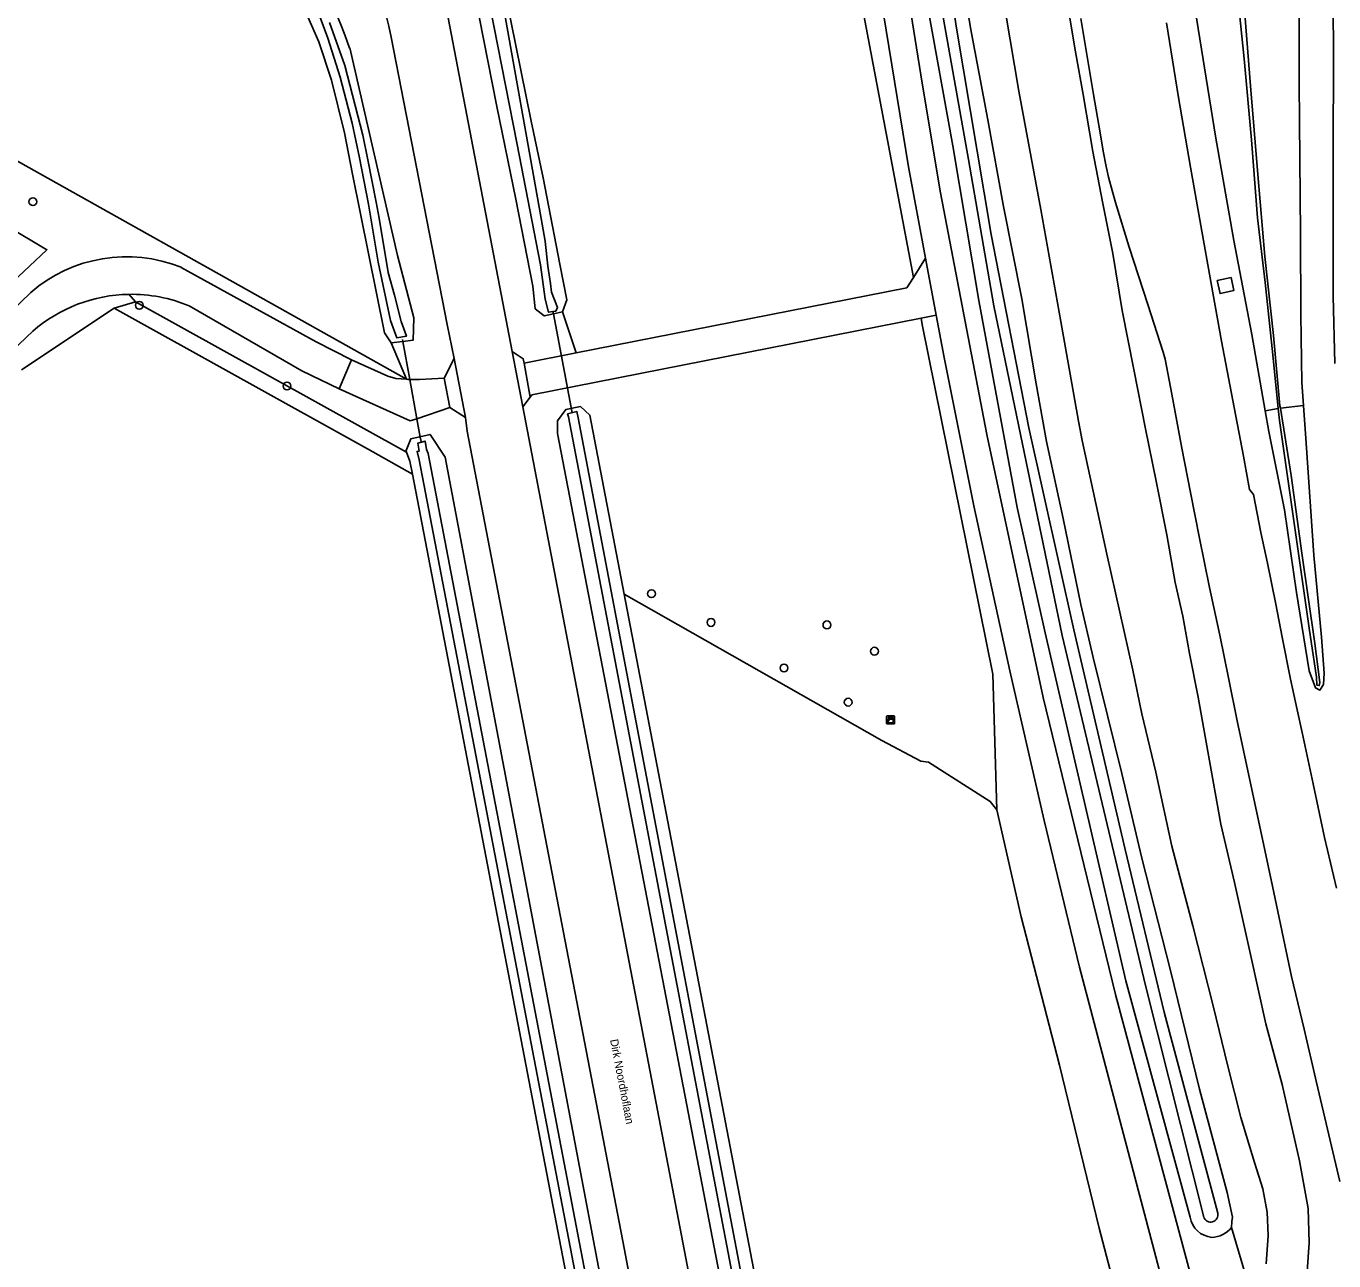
# Model space of a CAD drawing. Extents: x 155209 to 156823, y 385356 to 388482.
# Drawn here: x 155935 to 156098.5, y 387163 to 387317.3 of the extents above; entities that cross this region are included whole.
import ezdxf

# ---------------------------------------------------------------- set-up
doc = ezdxf.new("R2010")
doc.units = 0
for name, color, linetype in [('IMGEO_Berm_groen', 7, 'Continuous'), ('IMGEO_Boom', 7, 'Continuous'), ('IMGEO_Bouwland', 7, 'Continuous'), ('IMGEO_Duiker', 7, 'Continuous'), ('IMGEO_Grasland_overig', 7, 'Continuous'), ('IMGEO_Groenvoorziening', 7, 'Continuous'), ('IMGEO_Kast', 7, 'Continuous'), ('IMGEO_Openbare_ruimte_label', 7, 'Continuous'), ('IMGEO_Rijbaan_autoweg', 7, 'Continuous'), ('IMGEO_Rijbaan_lokaal_gesloten', 7, 'Continuous'), ('IMGEO_Rijbaan_lokaal_halfverhard', 7, 'Continuous'), ('IMGEO_Rijbaan_lokaal_onverhard', 7, 'Continuous'), ('IMGEO_Rijbaan_lokaal_open', 7, 'Continuous'), ('IMGEO_Struiken', 7, 'Continuous'), ('IMGEO_Waterloop', 7, 'Continuous')]:
    doc.layers.add(name, color=color, linetype=linetype)

msp = doc.modelspace()

# ---------------------------------------------------------------- linework, layer by layer
at = {"layer": 'IMGEO_Berm_groen'}
for points in [[(156061.62, 387476.82), (156062.41, 387469.09), (156063.7, 387456.14), (156064.93, 387442.53), (156066.52, 387426.48), (156068.23, 387413.01), (156069.84, 387398.7), (156071, 387388.31), (156072.33, 387377.8), (156074.13, 387364.9), (156075.6, 387353.79), (156077.6, 387340.98), (156079.75, 387327.89), (156081.71, 387315.66), (156083.71, 387303.27), (156085.96, 387290.47), (156088.22, 387278.73), (156089.87, 387269.17)], [(156091.79, 387269.51), (156091.73, 387269.83), (156090.93, 387278.61), (156089.85, 387288.48), (156088.98, 387298.73), (156088.03, 387309.82), (156087.34, 387318.75), (156086.57, 387326.51), (156086.11, 387337.21), (156085.57, 387346.45), (156085.53, 387353.44), (156085.58, 387363.28), (156085.48, 387373.43), (156085.38, 387384.38), (156085.39, 387393.87), (156085.5, 387398.4), (156085.73, 387399.51), (156086.28, 387400.46)], [(156095.62, 387391.04), (156095.67, 387380.15), (156095.25, 387368.03), (156095.02, 387355.31), (156094.88, 387346.18), (156094.52, 387336.14), (156094.14, 387326.16), (156094.14, 387318.25), (156094.11, 387310.18), (156094.22, 387300.65), (156094.28, 387291.34), (156094.35, 387281.23), (156094.46, 387272.73), (156094.68, 387269.84)], [(156091.51, 387269.47), (156090.82, 387276.17), (156089.88, 387285.21), (156088.93, 387293.32), (156088.19, 387303.06), (156087.26, 387313.19), (156086.23, 387323.35)], [(156064.83, 387322.06), (156066.18, 387314.05), (156067.13, 387308.73), (156068.35, 387301.58), (156069.57, 387295.29), (156070.85, 387288.86), (156072.01, 387281.71), (156073.46, 387274.35), (156074.91, 387266.93), (156076.27, 387260.41), (156077.57, 387253.69), (156078.65, 387247.72), (156079.57, 387243.53), (156080.41, 387238.88), (156081.52, 387233.39), (156082.94, 387225.44), (156084.32, 387217.55), (156086.06, 387210.27), (156088.06, 387201.26), (156089.96, 387192.59), (156092.02, 387185.03), (156094.18, 387175.46), (156095.27, 387169.51), (156095.39, 387165.23), (156095.04, 387160.42)], [(156085.62, 387285.86), (156083.89, 387285.47), (156084.25, 387283.85), (156085.98, 387284.24), (156085.62, 387285.86)], [(155947.88, 387283.75), (155948.71, 387282.8)], [(155946.02, 387282), (155934.44, 387274.3)], [(155948.71, 387282.8), (155946.02, 387282)], [(155948.71, 387282.8), (155982.58, 387264.03)], [(156089.87, 387269.17), (156090.32, 387266.61), (156092.28, 387256.8), (156093.78, 387246.51), (156095.36, 387236.69), (156096.17, 387234.57), (156096.72, 387234.3), (156097.16, 387235.01), (156097.27, 387236.41), (156096.9, 387240.92), (156095.95, 387251.17), (156095, 387265.15), (156094.68, 387269.84)], [(156091.79, 387269.51), (156093.12, 387261.1), (156094.44, 387251.42), (156096.1, 387240.13), (156096.69, 387235.24), (156096.63, 387234.85), (156096.34, 387234.9), (156096.31, 387235.92), (156095.38, 387242.03), (156093.61, 387254.26), (156091.67, 387267.98), (156091.51, 387269.47)], [(156020.54, 387071.32), (156022.07, 387071.71), (156023.15, 387072.76), (156023.19, 387074.38), (155987.41, 387263.41), (155985.52, 387266.24), (155983.11, 387265.71), (155982.51, 387264.23), (155982.58, 387264.03)]]:
    msp.add_lwpolyline(points, dxfattribs=at)
at = {"layer": 'IMGEO_Boom'}
for centre in [(155935.88, 387295.32), (155949.18, 387282.38), (155967.63, 387272.3), (156013.19, 387246.34), (156020.63, 387242.75), (156035.11, 387242.44), (156041.05, 387239.15), (156029.74, 387237.05), (156037.77, 387232.78)]:
    msp.add_circle(centre, 0.489, dxfattribs=at)
at = {"layer": 'IMGEO_Bouwland'}
for points in [[(155700.58, 387559.16), (155705.83, 387556.93), (155969.17, 387436.11), (155980.49, 387430.9), (156014.09, 387415.4), (156016.16, 387414.21), (156018.36, 387412.83), (156019.97, 387411.04), (156020.38, 387409.71), (156021.3, 387407.09), (156021.62, 387404.48), (156021.21, 387401.4), (156020.2, 387398.6), (155995.77, 387345.63), (155992.84, 387339.75), (155992.29, 387338.15), (155992.33, 387336.17), (155993.02, 387331.58), (155994.35, 387324.15), (155998.16, 387305.37), (155999.63, 387298.3), (156001.74, 387287.51), (156002.6, 387283.08), (156002.07, 387281.58)], [(156045.92, 387285.85), (156037.65, 387329.66), (156026.8, 387420.55), (156020.19, 387555.62)], [(155969.78, 387319.47), (155971.62, 387315.3), (155973.18, 387310.52), (155974.83, 387303.91), (155975.84, 387298.77), (155979.82, 387278.93), (155980.66, 387277.68)], [(155852.44, 387209.14), (155937.64, 387289.31), (155917.27, 387301.48), (155920.84, 387307.7), (155982.59, 387273.13)], [(155983.31, 387261.26), (155977.7, 387264.44), (155946.02, 387282)], [(156002.07, 387281.58), (156003.77, 387276.42)], [(156056.35, 387219.32), (156055.84, 387236.29), (156047.02, 387279.97), (156046.87, 387280.78)], [(155982.59, 387273.13), (155980.66, 387277.68)], [(156040.62, 387085.43), (156049.4, 387039.61), (156049.03, 387038.45), (156048.01, 387037.48), (156046.7, 387037.25), (156045.6, 387038.35), (156044.88, 387040.73), (156001.43, 387266.35), (156001.45, 387267.92), (156002.48, 387269.35), (156004.33, 387269.73), (156005.47, 387268.66), (156009.77, 387246.27)], [(155983.31, 387261.26), (156019.65, 387072.07), (156020.54, 387071.32)], [(156009.77, 387246.27), (156039.37, 387091.89)], [(156009.77, 387246.27), (156041.99, 387228.01), (156046.85, 387225.4), (156047.8, 387225.28), (156055.53, 387220.36), (156056.35, 387219.32)], [(156078.96, 387129.05), (156077.06, 387135.76), (156072.99, 387152.28), (156069.14, 387167.07), (156064.17, 387187.41), (156059.38, 387205.95), (156056.35, 387219.32)]]:
    msp.add_lwpolyline(points, dxfattribs=at)
at = {"layer": 'IMGEO_Duiker'}
for points in [[(156000.87, 387281.6), (156000.93, 387281.32), (156003.27, 387268.94)], [(155982.06, 387278.09), (155982.1, 387277.85), (155982.97, 387273.12), (155983.87, 387268.2), (155984.28, 387265.92), (155984.39, 387265.37)]]:
    msp.add_lwpolyline(points, dxfattribs=at)
at = {"layer": 'IMGEO_Grasland_overig'}
for points in [[(156085.66, 387167.13), (156085.73, 387167.9), (156085.79, 387168.45), (156085.12, 387171.5), (156081.69, 387184.41), (156078.03, 387199.27), (156074.47, 387213.29), (156071.98, 387223.87), (156068.39, 387238.38), (156066.86, 387244.97), (156064.64, 387255.74), (156062.57, 387265.36), (156061.25, 387272.56), (156059.48, 387283.2), (156057.16, 387294.73), (156055.2, 387305.56), (156053.06, 387317.03), (156051.56, 387326.11)], [(156090, 387162.62), (156090.26, 387166.15), (156090.13, 387169.04), (156089.57, 387171.99), (156088.55, 387175.26), (156086.83, 387180.87), (156085.22, 387187.3), (156083.39, 387194.86), (156080.83, 387204.83), (156078.22, 387214.79), (156076.2, 387224.02), (156074.47, 387231.32), (156073.33, 387236.78), (156070.1, 387251.29), (156067, 387265.48), (156066.57, 387267.88), (156064.33, 387280.36), (156061.83, 387294.35), (156059.1, 387309.12), (156056.92, 387322)], [(156080.49, 387168.45), (156072.47, 387197.97), (156062.39, 387241.43), (156058.9, 387257.1), (156054.08, 387282.98), (156050.84, 387302.29), (156047.64, 387320.03)], [(156095.73, 387133.19), (156085.66, 387167.13)]]:
    msp.add_lwpolyline(points, dxfattribs=at)
for centre, radius, start, end in [((156083.5, 387168.93), 3.04, 189.1217, 264.4738), ((156083.09, 387169.19), 3.29, 272.035, 321.3376)]:
    msp.add_arc(centre, radius, start, end, dxfattribs=at)
at = {"layer": 'IMGEO_Groenvoorziening'}
for points in [[(156002.07, 387281.58), (156000.93, 387281.32), (155999.78, 387281.05), (155998.63, 387281.95), (155998.35, 387284.75), (155997.67, 387288.39), (155996.23, 387295.64), (155993.85, 387307.21), (155991.64, 387318.41), (155989.37, 387330.86)], [(155980.66, 387277.68), (155982.1, 387277.85), (155983.39, 387278.01), (155983.5, 387280.81), (155981.46, 387288.59), (155975.47, 387314.53)], [(155982.58, 387264.03), (155983, 387262.89), (155983.31, 387261.26)]]:
    msp.add_lwpolyline(points, dxfattribs=at)
msp.add_arc((155897.75, 387286.71), 82.54, 19.6901, 30.7711, dxfattribs=at)
at = {"layer": 'IMGEO_Kast'}
for p, q in [((156042.57, 387230.14), (156042.57, 387230.98)), ((156042.57, 387230.98), (156042.57, 387230.14)), ((156042.65, 387231.06), (156043.49, 387231.06)), ((156043.49, 387231.06), (156042.65, 387231.06)), ((156043.5, 387230.06), (156042.66, 387230.06)), ((156042.66, 387230.06), (156043.5, 387230.06)), ((156043.57, 387230.99), (156043.57, 387230.15)), ((156043.57, 387230.15), (156043.57, 387230.99))]:
    msp.add_line(p, q, dxfattribs=at)
for points in [[(156042.77, 387230.85), (156043.37, 387230.85), (156043.37, 387230.77), (156042.77, 387230.77), (156042.77, 387230.85)], [(156042.77, 387230.68), (156043.37, 387230.68), (156043.37, 387230.19), (156042.77, 387230.19), (156042.77, 387230.68)]]:
    msp.add_lwpolyline(points, dxfattribs=at)
msp.add_circle((156042.85, 387230.53), 0.0377, dxfattribs=at)
for centre, start, end in [((156042.65, 387230.99), 92.4484, 184.2845), ((156042.65, 387230.99), 92.4484, 184.2845), ((156042.65, 387230.14), 182.4484, 274.2845), ((156042.65, 387230.14), 182.4484, 274.2845), ((156043.49, 387230.99), 2.4484, 94.2845), ((156043.49, 387230.99), 2.4484, 94.2845), ((156043.49, 387230.14), 272.4484, 4.2845), ((156043.49, 387230.14), 272.4484, 4.2845)]:
    msp.add_arc(centre, 0.0779, start, end, dxfattribs=at)
at = {"layer": 'IMGEO_Rijbaan_autoweg'}
for points in [[(156098.37, 387321.27), (156098.42, 387312.33), (156098.37, 387302.72), (156098.36, 387292.83), (156098.37, 387283.53), (156098.57, 387275.09)], [(156099.19, 387172.87), (156097.83, 387178.72), (156096.29, 387185.27), (156094.75, 387191.94), (156093.18, 387198.52), (156090.8, 387209.8), (156089.28, 387216.83), (156087.85, 387223.62), (156086.37, 387230.44), (156085.32, 387235.63), (156084.23, 387241.16), (156082.94, 387247.12), (156081.66, 387253.29), (156080.53, 387258.98), (156079.46, 387264.51), (156078.21, 387271.26), (156077.4, 387275.63), (156077.15, 387276.52), (156075.23, 387282.49), (156072.87, 387289.65), (156071.16, 387295.21), (156070.75, 387296.71), (156070.32, 387298.4), (156070.01, 387299.72), (156069.63, 387301.65), (156069.26, 387303.92), (156068.43, 387308.71), (156066.85, 387318.23)], [(156098.79, 387209.53), (156097.31, 387215.88), (156095.88, 387222.59), (156094.5, 387228.98), (156093.89, 387231.81), (156093.06, 387235.66), (156092.02, 387240.92), (156091.22, 387245.05), (156090.16, 387250.15), (156089.35, 387254), (156088.43, 387258.72), (156087.92, 387259.38), (156087.19, 387263.51), (156085.82, 387270.48), (156084.43, 387277.89), (156083.13, 387285.09), (156081.84, 387292.33), (156080.54, 387299.65), (156079.03, 387308.34), (156077.55, 387317.68)]]:
    msp.add_lwpolyline(points, dxfattribs=at)
at = {"layer": 'IMGEO_Rijbaan_lokaal_gesloten'}
for points in [[(156027.54, 387557.22), (156027.62, 387546.78), (156027.42, 387516.8), (156028.65, 387483.23), (156030.14, 387455.45), (156032.35, 387424.76), (156034.61, 387401.66), (156038.15, 387370.39), (156042.46, 387338.51), (156047.03, 387310.12), (156049.29, 387296.42), (156055.09, 387266.23), (156062.12, 387233.38), (156071.16, 387196.26), (156081.89, 387156.33), (156090.36, 387124.96), (156100.47, 387087.38), (156109.71, 387056.23)], [(156023.95, 387554.1), (156024.11, 387543.92), (156023.95, 387535.86), (156024.01, 387519.99), (156024.47, 387501.51), (156025.96, 387471.53), (156027.8, 387439.19), (156029.55, 387418.04), (156030.94, 387404.18), (156035.09, 387368.15), (156037.92, 387346.64), (156041.82, 387321.12), (156045.31, 387299.66), (156047.45, 387288.26)], [(155986.4, 387325.52), (155995.77, 387276.62)], [(155988.51, 387275.75), (155987.67, 387279.96), (155980.67, 387315.87)], [(156048.78, 387281.15), (156047.45, 387288.26)], [(156084.15, 387133.91), (156076.64, 387161.91), (156066.68, 387199.67), (156062.24, 387217.98), (156057.95, 387236.69), (156053.47, 387257.31), (156049.77, 387275.85), (156048.78, 387281.15)], [(155988.51, 387275.75), (155989.94, 387268.35)], [(155995.77, 387276.62), (155997.11, 387269.67)], [(155997.11, 387269.67), (156016.95, 387166.15), (156032.7, 387083.72), (156041.49, 387037.48), (156043.83, 387025.26), (156046, 387013.89), (156048.88, 386998.73), (156052.13, 386981.86), (156054.86, 386968.12)], [(156025.74, 387080.22), (156009.76, 387164.56), (155992.17, 387256.24), (155990.17, 387266.67), (155989.94, 387268.35)]]:
    msp.add_lwpolyline(points, dxfattribs=at)
msp.add_arc((155845.57, 387285.48), 138.48, 12.6792, 49.4239, dxfattribs=at)
at = {"layer": 'IMGEO_Rijbaan_lokaal_halfverhard'}
for points in [[(156047.45, 387288.26), (156045.92, 387285.85)], [(156003.77, 387276.42), (156045.09, 387284.55), (156045.92, 387285.85)], [(156046.87, 387280.78), (155998.24, 387271.2), (155998.01, 387270.89)], [(156046.87, 387280.78), (156048.78, 387281.15)], [(155975.71, 387275.56), (155974.17, 387271.92)], [(155982.59, 387273.13), (155981.23, 387273.25), (155980.25, 387273.52), (155975.71, 387275.56)], [(156003.77, 387276.42), (155997.29, 387275.14)], [(155982.59, 387273.13), (155982.72, 387273.12), (155982.97, 387273.12), (155984.18, 387273.11), (155987.28, 387273.29)], [(155974.17, 387271.92), (155983.02, 387267.92), (155983.87, 387268.2), (155987.99, 387269.6)]]:
    msp.add_lwpolyline(points, dxfattribs=at)
at = {"layer": 'IMGEO_Rijbaan_lokaal_onverhard'}
for points in [[(155954.4, 387287.12), (155971.27, 387277.81), (155975.71, 387275.56)], [(155830.95, 387186.71), (155832.39, 387187.53), (155834.38, 387189.06), (155861.21, 387213.3), (155900.6, 387250), (155933.07, 387281.51), (155935.61, 387283.98)], [(155974.17, 387271.92), (155969.49, 387274.19), (155955.4, 387282.31)], [(155935.88, 387279.15), (155905.19, 387250), (155811.33, 387161.02), (155799.75, 387150.14)]]:
    msp.add_lwpolyline(points, dxfattribs=at)
for centre, radius, start, end in [((155947.58, 387270.17), 18.28, 68.0909, 130.8991), ((155948.19, 387264.98), 18.77, 90.9503, 130.9761), ((155948.18, 387264.96), 18.79, 67.4114, 90.9339)]:
    msp.add_arc(centre, radius, start, end, dxfattribs=at)
at = {"layer": 'IMGEO_Rijbaan_lokaal_open'}
for points in [[(155987.28, 387273.29), (155988.51, 387275.75)], [(155997.29, 387275.14), (155997.16, 387275.69), (155995.77, 387276.62)], [(155997.29, 387275.14), (155998.01, 387270.89)], [(155987.99, 387269.6), (155987.28, 387273.29)], [(155998.01, 387270.89), (155997.11, 387269.67)], [(155989.94, 387268.35), (155987.99, 387269.6)]]:
    msp.add_lwpolyline(points, dxfattribs=at)
at = {"layer": 'IMGEO_Struiken'}
for points in [[(156091.51, 387269.47), (156089.87, 387269.17)], [(156094.68, 387269.84), (156091.79, 387269.51)]]:
    msp.add_lwpolyline(points, dxfattribs=at)
at = {"layer": 'IMGEO_Waterloop'}
for points in [[(156047.63, 387341.22), (156051.29, 387316.99), (156055.64, 387291.24), (156060.36, 387267.05), (156065.95, 387241.84), (156072.4, 387214.36), (156077.24, 387194.04), (156083.96, 387168.94)], [(156082.2, 387168.45), (156074.93, 387197.4), (156064.5, 387241.1), (156055.96, 387282.33), (156052.8, 387300.61), (156047.25, 387331.74)], [(155994.4, 387321.3), (155999.26, 387293.92), (155999.88, 387290.38), (156000.25, 387287.26), (156000.57, 387285.1), (156000.7, 387284.02), (156001.46, 387282.09), (156001.24, 387281.66), (156000.87, 387281.6), (156000.32, 387281.5), (155999.91, 387283.15), (155999.31, 387287.44), (155996.39, 387302.48), (155992.03, 387324.74)], [(155971.48, 387319.12), (155972.72, 387315.77), (155974.28, 387310.9), (155975.79, 387305.12), (155976.71, 387300.8), (155977.81, 387295.02), (155979.01, 387287.77), (155980.56, 387280.48), (155981.38, 387278.31), (155982.56, 387278.5), (155981.9, 387280.36), (155981.05, 387283.65), (155980.27, 387286.47), (155979.17, 387293.26), (155978.78, 387295.26), (155977.72, 387300.56), (155977.1, 387303.64), (155974.85, 387312.34), (155972.93, 387317.71)], [(156002.8, 387268.42), (156002.71, 387268.82), (156003.86, 387269.09), (156004.03, 387268.32), (156047.43, 387040.3), (156046.43, 387040.12), (156002.8, 387268.42)], [(155984.17, 387263.08), (155983.89, 387264.11), (155984.17, 387264.17), (155983.98, 387265.13), (155984.9, 387265.42), (155985.06, 387264.36), (155985.28, 387263.86), (156021.93, 387072.6), (156022.03, 387072.16), (156020.84, 387071.88), (156020.71, 387072.48), (155984.17, 387263.08)]]:
    msp.add_lwpolyline(points, dxfattribs=at)
msp.add_arc((156083.07, 387168.73), 0.912, 197.6383, 13.7261, dxfattribs=at)

# ---------------------------------------------------------------- texts
at = {"layer": 'IMGEO_Openbare_ruimte_label'}
msp.add_text('Dirk Noordhoflaan', height=1, rotation=280.8379, dxfattribs=at).set_placement((156008.01, 387190.58))

doc.saveas('drawing.dxf')
